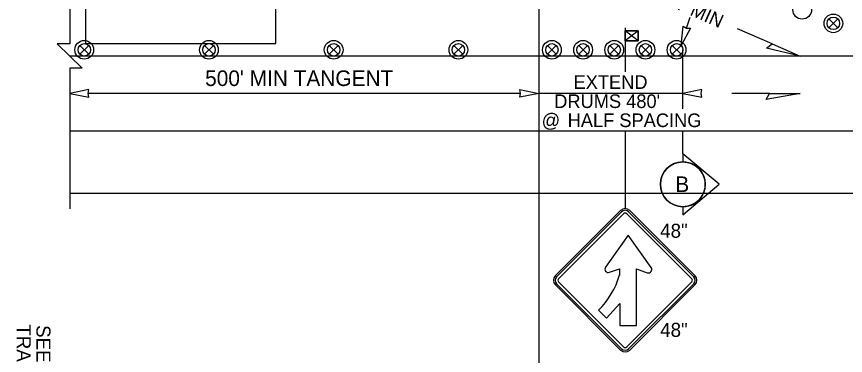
# Model space of a CAD drawing. Extents: x 99999 to 100116, y 99995 to 100013.
# Drawn here: x 100087.922 to 100092.176, y 100005.726 to 100007.467 of the extents above; entities that cross this region are included whole.
import ezdxf

# ---------------------------------------------------------------- set-up
doc = ezdxf.new("R2010")
doc.units = 0
for name, color, linetype in [('RD_MK_LineEdgeYellow', 7, 'Continuous'), ('RD_MK_LineLane', 7, 'Continuous'), ('SH_GI_SectionCut', 7, 'Continuous'), ('TR_SN_ConstructionSigns', 7, 'Continuous'), ('TR_WZ_PortableSignMount5ftMinBlk-Org', 7, 'Continuous'), ('TR_WZ_TrafficSafetyDrum', 7, 'Continuous'), ('TR_WZ_WorkZoneDetails', 7, 'Continuous'), ('TR_WZ_WorkZoneTextCurrent', 7, 'Continuous')]:
    doc.layers.add(name, color=color, linetype=linetype)

msp = doc.modelspace()

# ---------------------------------------------------------------- linework, layer by layer
at = {"layer": 'RD_MK_LineEdgeYellow'}
msp.add_line((100088.195, 100006.88), (100095.43, 100006.88), dxfattribs=at)
at = {"layer": 'RD_MK_LineLane'}
msp.add_lwpolyline([(100095.43, 100007.264), (100088.195, 100007.264)], dxfattribs=at)
at = {"layer": 'SH_GI_SectionCut'}
for p, q in [((100091.3414, 100006.761), (100091.3414, 100006.88)), ((100091.3414, 100006.761), (100091.3414, 100006.7203)), ((100091.5275, 100006.6051), (100091.3414, 100006.761)), ((100091.3414, 100006.4492), (100091.5275, 100006.6051)), ((100091.3414, 100006.4899), (100091.3414, 100006.4492))]:
    msp.add_line(p, q, dxfattribs=at)
msp.add_circle((100091.3414, 100006.6051), 0.1152, dxfattribs=at)
msp.add_circle((100091.3414, 100006.6051), 0.1152, dxfattribs=at)
for start, end in [(90.0028, 269.9984), (269.9984, 90.0028), (269.9984, 90.0028)]:
    msp.add_arc((100091.3414, 100006.6051), 0.1152, start, end, dxfattribs=at)
at = {"layer": 'TR_SN_ConstructionSigns'}
for p, q in [((100091.0214, 100006.4701), (100090.6873, 100006.136)), ((100091.0274, 100006.4642), (100090.6933, 100006.1301)), ((100090.7032, 100006.1201), (100091.0373, 100006.4542)), ((100091.0532, 100006.4542), (100091.3874, 100006.1201)), ((100091.3973, 100006.1301), (100091.0632, 100006.4642)), ((100091.4033, 100006.136), (100091.0692, 100006.4701)), ((100091.0612, 100006.3441), (100090.9447, 100006.1802)), ((100091.1791, 100006.1784), (100091.0612, 100006.3441)), ((100090.9652, 100006.1532), (100091.0171, 100006.1718)), ((100091.0171, 100006.1718), (100091.0171, 100006.1394)), ((100091.1039, 100005.8802), (100091.1039, 100006.1703)), ((100091.1039, 100006.1703), (100091.1588, 100006.1513)), ((100090.6933, 100006.0943), (100091.0274, 100005.7602)), ((100091.0373, 100005.7701), (100090.7032, 100006.1042)), ((100091.3874, 100006.1042), (100091.0532, 100005.7701)), ((100091.0632, 100005.7602), (100091.3973, 100006.0943)), ((100090.6873, 100006.0883), (100091.0214, 100005.7542)), ((100091.0692, 100005.7542), (100091.4033, 100006.0883)), ((100090.9494, 100005.9171), (100091.0186, 100005.9936)), ((100091.0186, 100005.9936), (100091.0186, 100005.8802)), ((100090.9082, 100005.9583), (100090.9494, 100005.9171)), ((100091.0186, 100005.8802), (100091.1039, 100005.8802))]:
    msp.add_line(p, q, dxfattribs=at)
for centre, radius, start, end in [((100091.0453, 100006.4463), 0.0338, 45, 135), ((100091.0453, 100006.4463), 0.0253, 45, 135), ((100091.0453, 100006.4463), 0.0113, 45, 135), ((100090.9592, 100006.17), 0.0177, 144.5862, 289.6669), ((100090.604, 100006.2645), 0.4316, 314.815, 343.157), ((100091.1646, 100006.1681), 0.0177, 250.8938, 35.4138), ((100090.7112, 100006.1122), 0.0338, 135, 225), ((100090.7112, 100006.1122), 0.0253, 135, 225), ((100090.7112, 100006.1122), 0.0113, 135, 225), ((100091.3794, 100006.1122), 0.0113, 315, 45), ((100091.3794, 100006.1122), 0.0253, 315, 45), ((100091.3794, 100006.1122), 0.0338, 315, 45), ((100091.0453, 100005.7781), 0.0338, 225, 315), ((100091.0453, 100005.7781), 0.0253, 225, 315), ((100091.0453, 100005.7781), 0.0113, 225, 315)]:
    msp.add_arc(centre, radius, start, end, dxfattribs=at)
at = {"layer": 'TR_WZ_PortableSignMount5ftMinBlk-Org'}
for p, q in [((100091.0453, 100007.408), (100091.0453, 100007.328)), ((100091.112, 100007.342), (100091.0453, 100007.394)), ((100091.112, 100007.394), (100091.0453, 100007.342)), ((100091.0786, 100007.368), (100091.0786, 100007.368)), ((100091.0788, 100007.368), (100091.0788, 100007.368))]:
    msp.add_line(p, q, dxfattribs=at)
for points in [[(100091.112, 100007.342), (100091.112, 100007.394), (100091.0453, 100007.394), (100091.0453, 100007.342)], [(100091.0453, 100007.394), (100091.112, 100007.394), (100091.112, 100007.342), (100091.0453, 100007.342)]]:
    msp.add_lwpolyline(points, close=True, dxfattribs=at)
at = {"layer": 'TR_WZ_TrafficSafetyDrum'}
for p, q in [((100092.0913, 100007.4092), (100092.1366, 100007.4545)), ((100092.1366, 100007.4092), (100092.0913, 100007.4545)), ((100088.2468, 100007.2734), (100088.292, 100007.3186)), ((100088.292, 100007.2734), (100088.2468, 100007.3186)), ((100088.8868, 100007.2734), (100088.932, 100007.3186)), ((100088.932, 100007.2734), (100088.8868, 100007.3186)), ((100089.5268, 100007.2734), (100089.572, 100007.3186)), ((100089.572, 100007.2734), (100089.5268, 100007.3186)), ((100090.1668, 100007.2734), (100090.212, 100007.3186)), ((100090.212, 100007.2734), (100090.1668, 100007.3186)), ((100090.6468, 100007.2734), (100090.692, 100007.3186)), ((100090.692, 100007.2734), (100090.6468, 100007.3186)), ((100090.8068, 100007.2734), (100090.852, 100007.3186)), ((100090.852, 100007.2734), (100090.8068, 100007.3186)), ((100090.9668, 100007.2734), (100091.012, 100007.3186)), ((100091.012, 100007.2734), (100090.9668, 100007.3186)), ((100091.1268, 100007.2734), (100091.172, 100007.3186)), ((100091.172, 100007.2734), (100091.1268, 100007.3186)), ((100091.2868, 100007.2734), (100091.332, 100007.3186)), ((100091.332, 100007.2734), (100091.2868, 100007.3186))]:
    msp.add_line(p, q, dxfattribs=at)
for centre, radius in [((100091.9539, 100007.5016), 0.048), ((100091.9539, 100007.5016), 0.048), ((100092.1139, 100007.4318), 0.048), ((100092.1139, 100007.4318), 0.048), ((100092.1139, 100007.4318), 0.032), ((100088.2694, 100007.296), 0.048), ((100088.2694, 100007.296), 0.048), ((100088.2694, 100007.296), 0.032), ((100088.9094, 100007.296), 0.048), ((100088.9094, 100007.296), 0.048), ((100088.9094, 100007.296), 0.032), ((100089.5494, 100007.296), 0.048), ((100089.5494, 100007.296), 0.048), ((100089.5494, 100007.296), 0.032), ((100090.1894, 100007.296), 0.048), ((100090.1894, 100007.296), 0.048), ((100090.1894, 100007.296), 0.032), ((100090.6694, 100007.296), 0.048), ((100090.6694, 100007.296), 0.048), ((100090.6694, 100007.296), 0.032), ((100090.8294, 100007.296), 0.048), ((100090.8294, 100007.296), 0.048), ((100090.8294, 100007.296), 0.032), ((100090.9894, 100007.296), 0.048), ((100090.9894, 100007.296), 0.048), ((100090.9894, 100007.296), 0.032), ((100091.1494, 100007.296), 0.048), ((100091.1494, 100007.296), 0.048), ((100091.1494, 100007.296), 0.032), ((100091.3094, 100007.296), 0.048), ((100091.3094, 100007.296), 0.048), ((100091.3094, 100007.296), 0.032)]:
    msp.add_circle(centre, radius, dxfattribs=at)
at = {"layer": 'TR_WZ_WorkZoneDetails'}
for p, q in [((100090.6024, 100009.294), (100090.6024, 100005.4763)), ((100091.3608, 100007.4078), (100091.3786, 100007.463)), ((100091.7994, 100007.3264), (100091.6223, 100007.403)), ((100091.0453, 100007.328), (100091.0453, 100007.183)), ((100091.3414, 100006.992), (100091.3414, 100007.296)), ((100090.5087, 100007.072), (100088.2887, 100007.072)), ((100091.3414, 100007.072), (100090.6024, 100007.072)), ((100091.7865, 100007.072), (100091.5936, 100007.072)), ((100091.0453, 100006.88), (100091.0453, 100006.48)), ((100088.195, 100006.56), (100095.43, 100006.56))]:
    msp.add_line(p, q, dxfattribs=at)
msp.add_lwpolyline([(100088.195, 100008.048), (100088.195, 100007.326), (100088.131, 100007.326), (100088.259, 100007.2021), (100088.195, 100007.2021), (100088.195, 100006.48)], dxfattribs=at)
for points in [[(100088.275, 100007.968), (100088.275, 100007.328), (100089.2533, 100007.328), (100089.2533, 100007.968)], [(100091.3333, 100007.3182), (100091.3437, 100007.4178), (100091.3608, 100007.4078), (100091.3805, 100007.4065)], [(100091.9437, 100007.264), (100091.7708, 100007.3052), (100091.7994, 100007.3264)], [(100088.195, 100007.072), (100088.2933, 100007.0528), (100088.2887, 100007.072), (100088.2933, 100007.0913)], [(100090.6024, 100007.072), (100090.5041, 100007.0528), (100090.5087, 100007.072), (100090.5041, 100007.0913)], [(100091.3414, 100007.072), (100091.4396, 100007.0528), (100091.4351, 100007.072), (100091.4396, 100007.0913)], [(100091.9437, 100007.072), (100091.7686, 100007.0412), (100091.7865, 100007.072)]]:
    msp.add_lwpolyline(points, close=True, dxfattribs=at)

# ---------------------------------------------------------------- texts
at = {"layer": 'SH_GI_SectionCut'}
msp.add_text('B', height=0.08, rotation=359.9906, dxfattribs=at).set_placement((100091.3027, 100006.5658))
at = {"layer": 'TR_SN_ConstructionSigns'}
for p in [(100091.2251, 100006.3307), (100091.2251, 100005.8216)]:
    msp.add_text('48"', height=0.072, rotation=360, dxfattribs=at).set_placement(p)
at = {"layer": 'TR_WZ_WorkZoneDetails'}
for s, p in [('TRAFFIC CONTROL PLAN', (100087.923, 100005.8862)), ('SEE ON-RAMP CLOSURE', (100088.0238, 100005.8822))]:
    msp.add_text(s, height=0.072, rotation=270, dxfattribs=at).set_placement(p)
at = {"layer": 'TR_WZ_WorkZoneTextCurrent'}
msp.add_text("14' MIN", height=0.07, rotation=335.8373, dxfattribs=at).set_placement((100091.2383, 100007.5369))
for s, height, p in [("500' MIN TANGENT", 0.08, (100088.8897, 100007.11)), ('EXTEND', 0.07, (100090.7804, 100007.095)), ("DRUMS 480'", 0.07, (100090.6813, 100006.997)), ('@', 0.07, (100090.6167, 100006.899)), ('HALF SPACING', 0.07, (100090.7502, 100006.899))]:
    msp.add_text(s, height=height, dxfattribs=at).set_placement(p)

doc.saveas('drawing.dxf')
